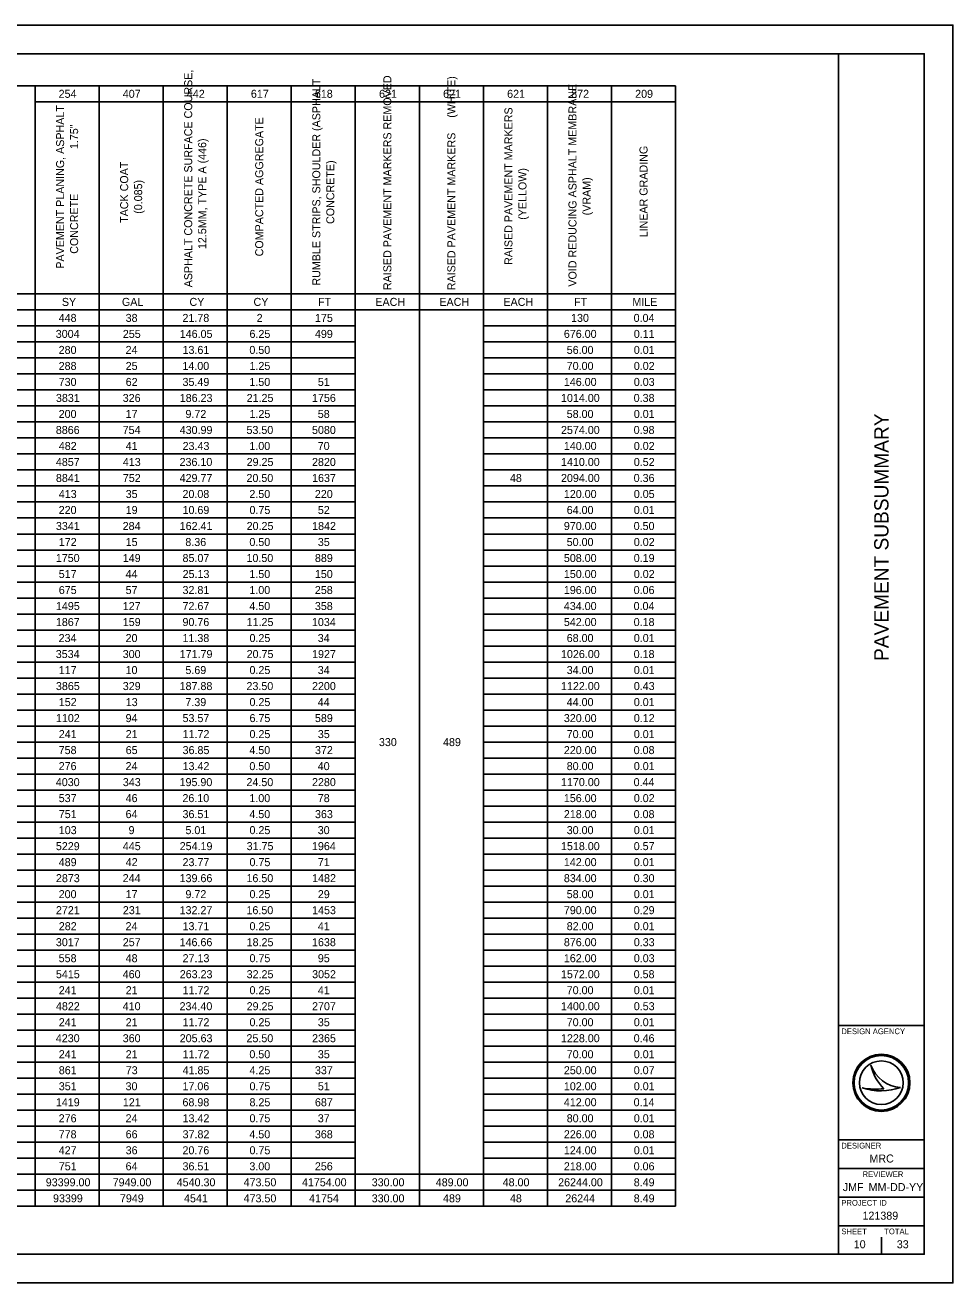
# Model space of a CAD drawing. Extents: x 0 to 34, y 0 to 22.
# Drawn here: x 17.78 to 34, y 0 to 22 of the extents above; entities that cross this region are included whole.
import ezdxf

# ---------------------------------------------------------------- set-up
doc = ezdxf.new("R2010")
doc.units = 0
for name, color, linetype in [('SH_Border', 7, 'Continuous'), ('SH_Cut_Line', 7, 'Continuous'), ('SH_Data', 7, 'Continuous'), ('SH_Text', 7, 'Continuous')]:
    doc.layers.add(name, color=color, linetype=linetype)

msp = doc.modelspace()

# ---------------------------------------------------------------- linework, layer by layer
at = {"layer": 'SH_Border'}
for p, q in [((32, 0.5), (32, 21.5)), ((32, 4.5), (33.5, 4.5)), ((32, 2.5), (33.5, 2.5)), ((32, 2), (33.5, 2)), ((32, 1.5), (33.5, 1.5)), ((32, 1), (33.5, 1))]:
    msp.add_line(p, q, dxfattribs=at)
msp.add_lwpolyline([(1.5, 21.5), (33.5, 21.5), (33.5, 0.5), (1.5, 0.5)], close=True, dxfattribs=at)
at = {"layer": 'SH_Cut_Line'}
msp.add_lwpolyline([(0, 0), (34, 0), (34, 22), (0, 22)], close=True, dxfattribs=at)
at = {"layer": 'SH_Data'}
for p, q in [((4.478, 20.939), (29.151, 20.939)), ((17.951, 20.939), (17.951, 20.659)), ((19.071, 20.939), (19.071, 1.339)), ((20.191, 20.939), (20.191, 1.339)), ((21.311, 20.939), (21.311, 1.339)), ((22.431, 20.939), (22.431, 1.899)), ((23.551, 20.939), (23.551, 1.339)), ((24.671, 20.939), (24.671, 1.339)), ((25.791, 20.939), (25.791, 1.339)), ((26.911, 20.939), (26.911, 1.339)), ((28.031, 20.939), (28.031, 17.299)), ((29.151, 20.939), (29.151, 1.339)), ((17.951, 20.659), (29.151, 20.659)), ((17.951, 20.659), (17.951, 1.339)), ((4.478, 17.299), (29.151, 17.299)), ((28.031, 17.299), (28.031, 17.019)), ((4.478, 17.019), (25.791, 17.019)), ((25.791, 17.019), (26.911, 17.019)), ((26.911, 17.019), (29.151, 17.019)), ((28.031, 17.019), (28.031, 1.339)), ((4.478, 16.739), (23.551, 16.739)), ((25.791, 16.739), (29.151, 16.739)), ((4.478, 16.459), (23.551, 16.459)), ((25.791, 16.459), (29.151, 16.459)), ((4.478, 16.179), (23.551, 16.179)), ((25.791, 16.179), (29.151, 16.179)), ((4.478, 15.899), (23.551, 15.899)), ((25.791, 15.899), (29.151, 15.899)), ((4.478, 15.619), (23.551, 15.619)), ((25.791, 15.619), (29.151, 15.619)), ((4.478, 15.339), (23.551, 15.339)), ((25.791, 15.339), (29.151, 15.339)), ((4.478, 15.059), (23.551, 15.059)), ((25.791, 15.059), (29.151, 15.059)), ((4.478, 14.779), (23.551, 14.779)), ((25.791, 14.779), (29.151, 14.779)), ((4.478, 14.499), (23.551, 14.499)), ((25.791, 14.499), (29.151, 14.499)), ((4.478, 14.219), (23.551, 14.219)), ((25.791, 14.219), (29.151, 14.219)), ((4.478, 13.939), (23.551, 13.939)), ((25.791, 13.939), (29.151, 13.939)), ((4.478, 13.659), (23.551, 13.659)), ((25.791, 13.659), (29.151, 13.659)), ((4.478, 13.379), (23.551, 13.379)), ((25.791, 13.379), (29.151, 13.379)), ((4.478, 13.099), (23.551, 13.099)), ((25.791, 13.099), (29.151, 13.099)), ((4.478, 12.819), (23.551, 12.819)), ((25.791, 12.819), (29.151, 12.819)), ((4.478, 12.539), (23.551, 12.539)), ((25.791, 12.539), (29.151, 12.539)), ((4.478, 12.259), (23.551, 12.259)), ((25.791, 12.259), (29.151, 12.259)), ((4.478, 11.979), (23.551, 11.979)), ((25.791, 11.979), (29.151, 11.979)), ((4.478, 11.699), (23.551, 11.699)), ((25.791, 11.699), (29.151, 11.699)), ((4.478, 11.419), (23.551, 11.419)), ((25.791, 11.419), (29.151, 11.419)), ((4.478, 11.139), (23.551, 11.139)), ((25.791, 11.139), (29.151, 11.139)), ((4.478, 10.859), (23.551, 10.859)), ((25.791, 10.859), (29.151, 10.859)), ((4.478, 10.579), (23.551, 10.579)), ((25.791, 10.579), (29.151, 10.579)), ((4.478, 10.299), (23.551, 10.299)), ((25.791, 10.299), (29.151, 10.299)), ((4.478, 10.019), (23.551, 10.019)), ((25.791, 10.019), (29.151, 10.019)), ((4.478, 9.739), (23.551, 9.739)), ((25.791, 9.739), (29.151, 9.739)), ((4.478, 9.459), (23.551, 9.459)), ((25.791, 9.459), (29.151, 9.459)), ((4.478, 9.179), (23.551, 9.179)), ((25.791, 9.179), (29.151, 9.179)), ((4.478, 8.899), (23.551, 8.899)), ((25.791, 8.899), (29.151, 8.899)), ((4.478, 8.619), (23.551, 8.619)), ((25.791, 8.619), (29.151, 8.619)), ((4.478, 8.339), (23.551, 8.339)), ((25.791, 8.339), (29.151, 8.339)), ((4.478, 8.059), (23.551, 8.059)), ((25.791, 8.059), (29.151, 8.059)), ((4.478, 7.779), (23.551, 7.779)), ((25.791, 7.779), (29.151, 7.779)), ((4.478, 7.499), (23.551, 7.499)), ((25.791, 7.499), (29.151, 7.499)), ((4.478, 7.219), (23.551, 7.219)), ((25.791, 7.219), (29.151, 7.219)), ((4.478, 6.939), (23.551, 6.939)), ((25.791, 6.939), (29.151, 6.939)), ((4.478, 6.659), (23.551, 6.659)), ((25.791, 6.659), (29.151, 6.659)), ((4.478, 6.379), (23.551, 6.379)), ((25.791, 6.379), (29.151, 6.379)), ((4.478, 6.099), (23.551, 6.099)), ((25.791, 6.099), (29.151, 6.099)), ((4.478, 5.819), (23.551, 5.819)), ((25.791, 5.819), (29.151, 5.819)), ((4.478, 5.539), (23.551, 5.539)), ((25.791, 5.539), (29.151, 5.539)), ((4.478, 5.259), (23.551, 5.259)), ((25.791, 5.259), (29.151, 5.259)), ((4.478, 4.979), (23.551, 4.979)), ((25.791, 4.979), (29.151, 4.979)), ((4.478, 4.699), (23.551, 4.699)), ((25.791, 4.699), (29.151, 4.699)), ((4.478, 4.419), (23.551, 4.419)), ((25.791, 4.419), (29.151, 4.419)), ((4.478, 4.139), (23.551, 4.139)), ((25.791, 4.139), (29.151, 4.139)), ((4.478, 3.859), (23.551, 3.859)), ((25.791, 3.859), (29.151, 3.859)), ((32.567, 3.81), (32.567, 3.81)), ((4.478, 3.579), (23.551, 3.579)), ((25.791, 3.579), (29.151, 3.579)), ((32.417, 3.41), (32.417, 3.41)), ((32.75, 3.5), (32.75, 3.5)), ((33.087, 3.419), (33.087, 3.419)), ((4.478, 3.299), (23.551, 3.299)), ((25.791, 3.299), (29.151, 3.299)), ((4.478, 3.019), (23.551, 3.019)), ((25.791, 3.019), (29.151, 3.019)), ((4.478, 2.739), (23.551, 2.739)), ((25.791, 2.739), (29.151, 2.739)), ((4.478, 2.459), (23.551, 2.459)), ((25.791, 2.459), (29.151, 2.459)), ((4.478, 2.179), (23.551, 2.179)), ((25.791, 2.179), (29.151, 2.179)), ((12.351, 1.899), (29.151, 1.899)), ((22.431, 1.899), (22.431, 1.339)), ((12.351, 1.619), (29.151, 1.619)), ((4.478, 1.339), (29.151, 1.339)), ((32.375, 0.675), (32.375, 0.675)), ((32.75, 0.5), (32.75, 0.8))]:
    msp.add_line(p, q, dxfattribs=at)
for radius in [0.5, 0.477, 0.477, 0.382]:
    msp.add_circle((32.75, 3.5), radius, dxfattribs=at)
for centre, radius, start, end in [((33.116, 3.998), 0.58, 198.9257, 198.9319), ((33.347, 3.97), 0.796, 191.6379, 191.6421), ((33.116, 3.998), 0.58, 198.9319, 267.1657), ((33.347, 3.97), 0.796, 191.6421, 226.0947), ((32.739, 4.37), 1.013, 251.4576, 290.0832), ((32.648, 4.654), 1.266, 259.4964, 259.4995), ((32.739, 4.37), 1.013, 251.4527, 251.4576), ((32.648, 4.654), 1.266, 259.4995, 276.6672)]:
    msp.add_arc(centre, radius, start, end, dxfattribs=at)

# ---------------------------------------------------------------- texts
msp.add_text('PAVEMENT SUBSUMMARY', height=0.25, rotation=90, dxfattribs=at).set_placement((32.875, 10.879))
for s, height, p in [('DESIGN AGENCY', 0.1, (32.05, 4.35)), ('DESIGNER', 0.1, (32.05, 2.35)), ('MRC', 0.14, (32.541, 2.105)), ('REVIEWER', 0.1, (32.422, 1.85)), ('JMF', 0.14, (32.075, 1.605)), ('MM-DD-YY', 0.14, (32.527, 1.605)), ('PROJECT ID', 0.1, (32.05, 1.35)), ('121389', 0.14, (32.42, 1.105)), ('SHEET', 0.1, (32.05, 0.85)), ('TOTAL', 0.1, (32.8, 0.85)), ('10', 0.14, (32.267, 0.605)), ('33', 0.14, (33.02, 0.605))]:
    msp.add_text(s, height=height, dxfattribs=at).set_placement(p)
at = {"layer": 'SH_Text'}
for s, p in [('ASPHALT CONCRETE SURFACE COURSE, ', (20.699, 17.414)), ('RUMBLE STRIPS, SHOULDER (ASPHALT ', (22.939, 17.444)), ('RAISED PAVEMENT MARKERS REMOVED', (24.181, 17.366)), ('RAISED PAVEMENT MARKERS     (WHITE)', (25.301, 17.363)), ('VOID REDUCING ASPHALT MEMBRANE ', (27.419, 17.426)), ('PAVEMENT PLANING, ASPHALT ', (18.459, 17.74)), ('RAISED PAVEMENT MARKERS     ', (26.299, 17.805)), ('CONCRETE               1.75"', (18.704, 18.001)), ('COMPACTED AGGREGATE', (21.941, 17.955)), ('12.5MM, TYPE A (446)', (20.944, 18.083)), ('LINEAR GRADING', (28.661, 18.288)), ('TACK COAT                                                           ', (19.579, 18.541)), ('CONCRETE)', (23.184, 18.522)), ('(YELLOW)', (26.544, 18.595)), ('(0.085)', (19.824, 18.7)), ('(VRAM)', (27.664, 18.673))]:
    msp.add_text(s, height=0.14, rotation=90, dxfattribs=at).set_placement(p)
for s, p in [('254', (18.363, 20.729)), ('407', (19.485, 20.729)), ('442', (20.606, 20.729)), ('617', (21.725, 20.729)), ('618', (22.844, 20.729)), ('621', (23.966, 20.729)), ('621', (25.086, 20.729)), ('621', (26.206, 20.729)), ('872', (27.326, 20.729)), ('209', (28.445, 20.729)), ('SY', (18.42, 17.089)), ('GAL', (19.47, 17.089)), ('CY', (20.651, 17.089)), ('CY', (21.771, 17.089)), ('FT', (22.898, 17.089)), ('EACH', (23.901, 17.089)), ('EACH', (25.021, 17.089)), ('EACH', (26.141, 17.089)), ('FT', (27.378, 17.089)), ('MILE', (28.396, 17.089)), ('448', (18.364, 16.809)), ('38', (19.535, 16.809)), ('21.78', (20.529, 16.809)), ('2', (21.826, 16.809)), ('175', (22.846, 16.809)), ('130', (27.324, 16.809)), ('0.04', (28.418, 16.809)), ('3004', (18.313, 16.529)), ('255', (19.486, 16.529)), ('146.05', (20.481, 16.529)), ('6.25', (21.701, 16.529)), ('499', (22.845, 16.529)), ('676.00', (27.198, 16.529)), ('0.11', (28.421, 16.529)), ('280', (18.364, 16.249)), ('24', (19.534, 16.249)), ('13.61', (20.53, 16.249)), ('0.50', (21.699, 16.249)), ('56.00', (27.248, 16.249)), ('0.01', (28.421, 16.249)), ('288', (18.364, 15.969)), ('25', (19.536, 15.969)), ('14.00', (20.528, 15.969)), ('1.25', (21.701, 15.969)), ('70.00', (27.248, 15.969)), ('0.02', (28.421, 15.969)), ('730', (18.364, 15.689)), ('62', (19.536, 15.689)), ('35.49', (20.53, 15.689)), ('1.50', (21.699, 15.689)), ('51', (22.896, 15.689)), ('146.00', (27.198, 15.689)), ('0.03', (28.421, 15.689)), ('3831', (18.316, 15.409)), ('326', (19.484, 15.409)), ('186.23', (20.481, 15.409)), ('21.25', (21.651, 15.409)), ('1756', (22.794, 15.409)), ('1014.00', (27.148, 15.409)), ('0.38', (28.419, 15.409)), ('200', (18.364, 15.129)), ('17', (19.535, 15.129)), ('9.72', (20.581, 15.129)), ('1.25', (21.701, 15.129)), ('58', (22.895, 15.129)), ('58.00', (27.248, 15.129)), ('0.01', (28.421, 15.129)), ('8866', (18.314, 14.849)), ('754', (19.483, 14.849)), ('430.99', (20.48, 14.849)), ('53.50', (21.648, 14.849)), ('5080', (22.794, 14.849)), ('2574.00', (27.148, 14.849)), ('0.98', (28.419, 14.849)), ('482', (18.366, 14.569)), ('41', (19.536, 14.569)), ('23.43', (20.531, 14.569)), ('1.00', (21.699, 14.569)), ('70', (22.894, 14.569)), ('140.00', (27.198, 14.569)), ('0.02', (28.421, 14.569)), ('4857', (18.315, 14.289)), ('413', (19.486, 14.289)), ('236.10', (20.478, 14.289)), ('29.25', (21.651, 14.289)), ('2820', (22.794, 14.289)), ('1410.00', (27.148, 14.289)), ('0.52', (28.421, 14.289)), ('8841', (18.316, 14.009)), ('752', (19.486, 14.009)), ('429.77', (20.479, 14.009)), ('20.50', (21.648, 14.009)), ('1637', (22.795, 14.009)), ('48', (26.255, 14.009)), ('2094.00', (27.148, 14.009)), ('0.36', (28.419, 14.009)), ('413', (18.366, 13.729)), ('35', (19.536, 13.729)), ('20.08', (20.529, 13.729)), ('2.50', (21.699, 13.729)), ('220', (22.844, 13.729)), ('120.00', (27.198, 13.729)), ('0.05', (28.421, 13.729)), ('220', (18.364, 13.449)), ('19', (19.536, 13.449)), ('10.69', (20.53, 13.449)), ('0.75', (21.701, 13.449)), ('52', (22.896, 13.449)), ('64.00', (27.248, 13.449)), ('0.01', (28.421, 13.449)), ('3341', (18.316, 13.169)), ('284', (19.483, 13.169)), ('162.41', (20.48, 13.169)), ('20.25', (21.651, 13.169)), ('1842', (22.796, 13.169)), ('970.00', (27.198, 13.169)), ('0.50', (28.419, 13.169)), ('172', (18.366, 12.889)), ('15', (19.536, 12.889)), ('8.36', (20.579, 12.889)), ('0.50', (21.699, 12.889)), ('35', (22.896, 12.889)), ('50.00', (27.248, 12.889)), ('0.02', (28.421, 12.889)), ('1750', (18.314, 12.609)), ('149', (19.485, 12.609)), ('85.07', (20.53, 12.609)), ('10.50', (21.648, 12.609)), ('889', (22.845, 12.609)), ('508.00', (27.198, 12.609)), ('0.19', (28.42, 12.609)), ('517', (18.365, 12.329)), ('44', (19.534, 12.329)), ('25.13', (20.531, 12.329)), ('1.50', (21.699, 12.329)), ('150', (22.844, 12.329)), ('150.00', (27.198, 12.329)), ('0.02', (28.421, 12.329)), ('675', (18.366, 12.049)), ('57', (19.535, 12.049)), ('32.81', (20.53, 12.049)), ('1.00', (21.699, 12.049)), ('258', (22.844, 12.049)), ('196.00', (27.198, 12.049)), ('0.06', (28.419, 12.049)), ('1495', (18.316, 11.769)), ('127', (19.485, 11.769)), ('72.67', (20.53, 11.769)), ('4.50', (21.699, 11.769)), ('358', (22.844, 11.769)), ('434.00', (27.198, 11.769)), ('0.04', (28.418, 11.769)), ('1867', (18.315, 11.489)), ('159', (19.485, 11.489)), ('90.76', (20.529, 11.489)), ('11.25', (21.651, 11.489)), ('1034', (22.793, 11.489)), ('542.00', (27.198, 11.489)), ('0.18', (28.419, 11.489)), ('234', (18.363, 11.209)), ('20', (19.534, 11.209)), ('11.38', (20.529, 11.209)), ('0.25', (21.701, 11.209)), ('34', (22.894, 11.209)), ('68.00', (27.248, 11.209)), ('0.01', (28.421, 11.209)), ('3534', (18.313, 10.929)), ('300', (19.484, 10.929)), ('171.79', (20.48, 10.929)), ('20.75', (21.651, 10.929)), ('1927', (22.795, 10.929)), ('1026.00', (27.148, 10.929)), ('0.18', (28.419, 10.929)), ('117', (18.365, 10.649)), ('10', (19.534, 10.649)), ('5.69', (20.58, 10.649)), ('0.25', (21.701, 10.649)), ('34', (22.894, 10.649)), ('34.00', (27.248, 10.649)), ('0.01', (28.421, 10.649)), ('3865', (18.316, 10.369)), ('329', (19.485, 10.369)), ('187.88', (20.479, 10.369)), ('23.50', (21.648, 10.369)), ('2200', (22.794, 10.369)), ('1122.00', (27.148, 10.369)), ('0.43', (28.421, 10.369)), ('152', (18.366, 10.089)), ('13', (19.537, 10.089)), ('7.39', (20.58, 10.089)), ('0.25', (21.701, 10.089)), ('44', (22.894, 10.089)), ('44.00', (27.248, 10.089)), ('0.01', (28.421, 10.089)), ('1102', (18.316, 9.809)), ('94', (19.534, 9.809)), ('53.57', (20.53, 9.809)), ('6.75', (21.701, 9.809)), ('589', (22.845, 9.809)), ('320.00', (27.198, 9.809)), ('0.12', (28.421, 9.809)), ('241', (18.366, 9.529)), ('21', (19.536, 9.529)), ('11.72', (20.531, 9.529)), ('0.25', (21.701, 9.529)), ('35', (22.896, 9.529)), ('330', (23.964, 9.389)), ('489', (25.085, 9.389)), ('70.00', (27.248, 9.529)), ('0.01', (28.421, 9.529)), ('758', (18.364, 9.249)), ('65', (19.536, 9.249)), ('36.85', (20.531, 9.249)), ('4.50', (21.699, 9.249)), ('372', (22.846, 9.249)), ('220.00', (27.198, 9.249)), ('0.08', (28.419, 9.249)), ('276', (18.364, 8.969)), ('24', (19.534, 8.969)), ('13.42', (20.531, 8.969)), ('0.50', (21.699, 8.969)), ('40', (22.894, 8.969)), ('80.00', (27.248, 8.969)), ('0.01', (28.421, 8.969)), ('4030', (18.314, 8.689)), ('343', (19.486, 8.689)), ('195.90', (20.478, 8.689)), ('24.50', (21.648, 8.689)), ('2280', (22.794, 8.689)), ('1170.00', (27.148, 8.689)), ('0.44', (28.418, 8.689)), ('537', (18.365, 8.409)), ('46', (19.535, 8.409)), ('26.10', (20.528, 8.409)), ('1.00', (21.699, 8.409)), ('78', (22.895, 8.409)), ('156.00', (27.198, 8.409)), ('0.02', (28.421, 8.409)), ('751', (18.366, 8.129)), ('64', (19.534, 8.129)), ('36.51', (20.53, 8.129)), ('4.50', (21.699, 8.129)), ('363', (22.846, 8.129)), ('218.00', (27.198, 8.129)), ('0.08', (28.419, 8.129)), ('103', (18.366, 7.849)), ('9', (19.586, 7.849)), ('5.01', (20.581, 7.849)), ('0.25', (21.701, 7.849)), ('30', (22.894, 7.849)), ('30.00', (27.248, 7.849)), ('0.01', (28.421, 7.849)), ('5229', (18.315, 7.569)), ('445', (19.486, 7.569)), ('254.19', (20.48, 7.569)), ('31.75', (21.651, 7.569)), ('1964', (22.793, 7.569)), ('1518.00', (27.148, 7.569)), ('0.57', (28.42, 7.569)), ('489', (18.365, 7.289)), ('42', (19.536, 7.289)), ('23.77', (20.53, 7.289)), ('0.75', (21.701, 7.289)), ('71', (22.896, 7.289)), ('142.00', (27.198, 7.289)), ('0.01', (28.421, 7.289)), ('2873', (18.316, 7.009)), ('244', (19.483, 7.009)), ('139.66', (20.479, 7.009)), ('16.50', (21.648, 7.009)), ('1482', (22.796, 7.009)), ('834.00', (27.198, 7.009)), ('0.30', (28.419, 7.009)), ('200', (18.364, 6.729)), ('17', (19.535, 6.729)), ('9.72', (20.581, 6.729)), ('0.25', (21.701, 6.729)), ('29', (22.896, 6.729)), ('58.00', (27.248, 6.729)), ('0.01', (28.421, 6.729)), ('2721', (18.316, 6.449)), ('231', (19.486, 6.449)), ('132.27', (20.479, 6.449)), ('16.50', (21.648, 6.449)), ('1453', (22.796, 6.449)), ('790.00', (27.198, 6.449)), ('0.29', (28.42, 6.449)), ('282', (18.366, 6.169)), ('24', (19.534, 6.169)), ('13.71', (20.53, 6.169)), ('0.25', (21.701, 6.169)), ('41', (22.896, 6.169)), ('82.00', (27.248, 6.169)), ('0.01', (28.421, 6.169)), ('3017', (18.315, 5.889)), ('257', (19.485, 5.889)), ('146.66', (20.479, 5.889)), ('18.25', (21.651, 5.889)), ('1638', (22.794, 5.889)), ('876.00', (27.198, 5.889)), ('0.33', (28.421, 5.889)), ('558', (18.364, 5.609)), ('48', (19.535, 5.609)), ('27.13', (20.531, 5.609)), ('0.75', (21.701, 5.609)), ('95', (22.896, 5.609)), ('162.00', (27.198, 5.609)), ('0.03', (28.421, 5.609)), ('5415', (18.316, 5.329)), ('460', (19.484, 5.329)), ('263.23', (20.481, 5.329)), ('32.25', (21.651, 5.329)), ('3052', (22.796, 5.329)), ('1572.00', (27.148, 5.329)), ('0.58', (28.419, 5.329)), ('241', (18.366, 5.049)), ('21', (19.536, 5.049)), ('11.72', (20.531, 5.049)), ('0.25', (21.701, 5.049)), ('41', (22.896, 5.049)), ('70.00', (27.248, 5.049)), ('0.01', (28.421, 5.049)), ('4822', (18.316, 4.769)), ('410', (19.484, 4.769)), ('234.40', (20.478, 4.769)), ('29.25', (21.651, 4.769)), ('2707', (22.795, 4.769)), ('1400.00', (27.148, 4.769)), ('0.53', (28.421, 4.769)), ('241', (18.366, 4.489)), ('21', (19.536, 4.489)), ('11.72', (20.531, 4.489)), ('0.25', (21.701, 4.489)), ('35', (22.896, 4.489)), ('70.00', (27.248, 4.489)), ('0.01', (28.421, 4.489)), ('4230', (18.314, 4.209)), ('360', (19.484, 4.209)), ('205.63', (20.481, 4.209)), ('25.50', (21.648, 4.209)), ('2365', (22.796, 4.209)), ('1228.00', (27.148, 4.209)), ('0.46', (28.419, 4.209)), ('241', (18.366, 3.929)), ('21', (19.536, 3.929)), ('11.72', (20.531, 3.929)), ('0.50', (21.699, 3.929)), ('35', (22.896, 3.929)), ('70.00', (27.248, 3.929)), ('0.01', (28.421, 3.929)), ('861', (18.366, 3.649)), ('73', (19.537, 3.649)), ('41.85', (20.531, 3.649)), ('4.25', (21.701, 3.649)), ('337', (22.845, 3.649)), ('250.00', (27.198, 3.649)), ('0.07', (28.42, 3.649)), ('351', (18.366, 3.369)), ('30', (19.534, 3.369)), ('17.06', (20.529, 3.369)), ('0.75', (21.701, 3.369)), ('51', (22.896, 3.369)), ('102.00', (27.198, 3.369)), ('0.01', (28.421, 3.369)), ('1419', (18.315, 3.089)), ('121', (19.486, 3.089)), ('68.98', (20.529, 3.089)), ('8.25', (21.701, 3.089)), ('687', (22.845, 3.089)), ('412.00', (27.198, 3.089)), ('0.14', (28.418, 3.089)), ('276', (18.364, 2.809)), ('24', (19.534, 2.809)), ('13.42', (20.531, 2.809)), ('0.75', (21.701, 2.809)), ('37', (22.895, 2.809)), ('80.00', (27.248, 2.809)), ('0.01', (28.421, 2.809)), ('778', (18.364, 2.529)), ('66', (19.535, 2.529)), ('37.82', (20.531, 2.529)), ('4.50', (21.699, 2.529)), ('368', (22.844, 2.529)), ('226.00', (27.198, 2.529)), ('0.08', (28.419, 2.529)), ('427', (18.365, 2.249)), ('36', (19.535, 2.249)), ('20.76', (20.529, 2.249)), ('0.75', (21.701, 2.249)), ('124.00', (27.198, 2.249)), ('0.01', (28.421, 2.249)), ('751', (18.366, 1.969)), ('64', (19.534, 1.969)), ('36.51', (20.53, 1.969)), ('3.00', (21.699, 1.969)), ('256', (22.844, 1.969)), ('218.00', (27.198, 1.969)), ('0.06', (28.419, 1.969)), ('93399.00', (18.138, 1.689)), ('7949.00', (19.308, 1.689)), ('4540.30', (20.428, 1.689)), ('473.50', (21.598, 1.689)), ('41754.00', (22.618, 1.689)), ('330.00', (23.838, 1.689)), ('489.00', (24.958, 1.689)), ('48.00', (26.128, 1.689)), ('26244.00', (27.098, 1.689)), ('8.49', (28.42, 1.689)), ('93399', (18.265, 1.409)), ('7949', (19.435, 1.409)), ('4541', (20.556, 1.409)), ('473.50', (21.598, 1.409)), ('41754', (22.743, 1.409)), ('330.00', (23.838, 1.409)), ('489', (25.085, 1.409)), ('48', (26.255, 1.409)), ('26244', (27.223, 1.409)), ('8.49', (28.42, 1.409))]:
    msp.add_text(s, height=0.14, dxfattribs=at).set_placement(p)

doc.saveas('drawing.dxf')
